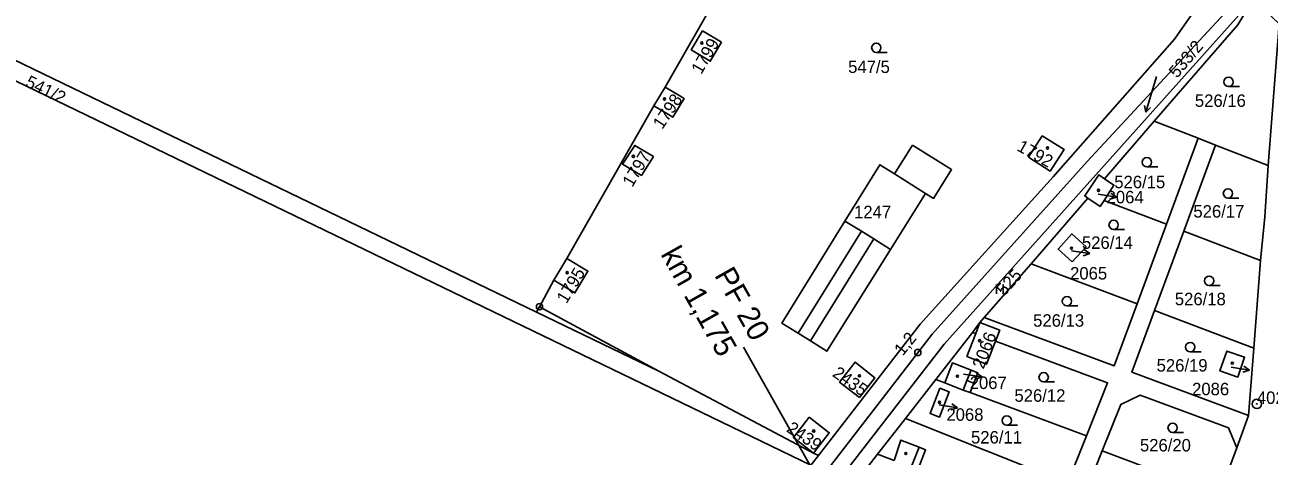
# Model space of a CAD drawing. Extents: x -555757 to -553364, y -1100723 to -1096439.
# Drawn here: x -554058.6 to -553858.9, y -1099803.9 to -1099734.7 of the extents above; entities that cross this region are included whole.
import ezdxf

# ---------------------------------------------------------------- set-up
doc = ezdxf.new("R2010")
doc.units = 0
for name, color, linetype in [('00_NÁVRH - 0.18 mm', 7, 'Continuous'), ('00_NÁVRH - 0.50 mm', 7, 'Continuous'), ('00_NÁVRH - Popis', 7, 'Continuous'), ('00_NÁVRH - Řezy', 7, 'Continuous'), ('BUDOVY', 7, 'Continuous'), ('C$SLO$PARCELY', 7, 'Continuous'), ('CISLO_PBPP', 7, 'Continuous'), ('HRANICE$PARCELY', 7, 'Continuous'), ('HRANICE$POROSTU', 7, 'Continuous'), ('PLOTY', 7, 'Continuous'), ('SLOUPY', 7, 'Continuous'), ('SLUCKOV$$C$RA', 7, 'Continuous'), ('STROMY', 7, 'Continuous'), ('VSTUP', 7, 'Continuous'), ('ZNA$KY$KULTUR', 7, 'Continuous')]:
    doc.layers.add(name, color=color, linetype=linetype)

# ---------------------------------------------------------------- blocks, each defined once
blk = doc.blocks.new('1$01')
at = {"layer": 'SLOUPY'}
for radius in [0.75, 0.032]:
    blk.add_circle((0, 0), radius, dxfattribs=at)
blk = doc.blocks.new('4$02')
at = {"layer": 'SLOUPY'}
blk.add_circle((0, 0), 0.175, dxfattribs=at)
blk = doc.blocks.new('1029')
at = {"layer": 'PLOTY'}
for p, q in [((0, 0), (2.964, -0.468)), ((2.964, -0.468), (2.052, 0.182)), ((2.964, -0.468), (1.897, -0.807))]:
    blk.add_line(p, q, dxfattribs=at)
blk = doc.blocks.new('3$04')
at = {"layer": 'ZNA$KY$KULTUR'}
blk.add_line((0.01, 0), (1.76, 0), dxfattribs=at)
blk.add_circle((0.01, 0.75), 0.75, dxfattribs=at)
blk = doc.blocks.new('3$06')
at = {"layer": 'SLOUPY'}
for p, q in [((-0.517, 0.235), (-0.517, 1.735)), ((0.517, 0.235), (0.517, 1.735))]:
    blk.add_line(p, q, dxfattribs=at)
blk = doc.blocks.new('8$02')
at = {"layer": 'ZNA$KY$KULTUR'}
for p, q in [((0.864, 2.855), (-0.89, -2.882)), ((-0.89, -2.882), (-1.083, -1.802)), ((-0.89, -2.882), (-0.125, -2.095))]:
    blk.add_line(p, q, dxfattribs=at)
blk = doc.blocks.new('1$05')
at = {"layer": 'SLOUPY'}
for radius in [0.5, 0.032]:
    blk.add_circle((0, 0), radius, dxfattribs=at)

msp = doc.modelspace()

# ---------------------------------------------------------------- linework, layer by layer
at = {"layer": '00_NÁVRH - 0.18 mm'}
msp.add_lwpolyline([(-554021.29, -1099939.52), (-554013.83, -1099925), (-554000.19, -1099901.94), (-553991.44, -1099884.82), (-553981.64, -1099867.37), (-553978.87, -1099863.78), (-553964.23, -1099845.81), (-553946.91, -1099823.19), (-553931.16, -1099807.8), (-553913.02, -1099784.31), (-553888.14, -1099756.58), (-553861.85, -1099728.23)], dxfattribs=at)
at = {"layer": '00_NÁVRH - 0.50 mm'}
msp.add_circle((-553915.3, -1099787.26), 0.5, dxfattribs=at)
at = {"layer": '00_NÁVRH - Řezy'}
msp.add_line((-553943.26, -1099786.41), (-553928.62, -1099812.39), dxfattribs=at)
at = {"layer": 'HRANICE$PARCELY'}
for p, q in [((-553930.27, -1099699.87), (-553955.86, -1099744.63)), ((-554139.3, -1099705.39), (-553932.48, -1099805.38)), ((-553955.86, -1099744.63), (-553957.65, -1099747.64)), ((-553957.65, -1099747.64), (-553971.65, -1099772.17)), ((-553885.34, -1099759.37), (-553877.35, -1099750.14)), ((-553870.34, -1099752.87), (-553877.35, -1099750.14)), ((-553875.42, -1099766.68), (-553870.34, -1099752.87)), ((-553867.55, -1099753.96), (-553872.62, -1099767.76)), ((-553870.34, -1099752.87), (-553867.55, -1099753.96)), ((-553867.55, -1099753.96), (-553859.1, -1099757.24)), ((-553897.14, -1099773), (-553888.02, -1099762.47)), ((-553875.42, -1099766.68), (-553885.42, -1099762.83)), ((-553880.12, -1099779.46), (-553875.42, -1099766.68)), ((-553872.62, -1099767.76), (-553877.31, -1099780.53)), ((-553872.62, -1099767.76), (-553860.3, -1099772.5)), ((-553971.65, -1099772.17), (-553973.74, -1099775.66)), ((-553904.64, -1099781.66), (-553897.14, -1099773)), ((-553880.12, -1099779.46), (-553897.14, -1099773)), ((-553861.4, -1099786.56), (-553860.3, -1099772.5)), ((-553973.74, -1099775.66), (-553976.03, -1099779.92)), ((-553905.33, -1099782.46), (-553904.64, -1099781.66)), ((-553877.31, -1099780.53), (-553861.4, -1099786.56)), ((-553912.43, -1099791.58), (-553906.55, -1099784.03)), ((-553905.33, -1099782.46), (-553906.55, -1099784.03)), ((-553862.25, -1099797.38), (-553861.4, -1099786.56)), ((-553917.29, -1099797.84), (-553912.43, -1099791.58)), ((-553910.96, -1099792.15), (-553912.43, -1099791.58)), ((-553888.24, -1099800.64), (-553906.93, -1099793.71)), ((-553921.77, -1099803.59), (-553917.29, -1099797.84)), ((-553891.27, -1099808.26), (-553917.29, -1099797.84)), ((-553864.13, -1099802.55), (-553862.25, -1099797.38)), ((-553891.27, -1099808.26), (-553888.24, -1099800.64)), ((-553931.27, -1099803.82), (-553932.48, -1099805.38)), ((-553925.95, -1099808.97), (-553921.77, -1099803.59)), ((-553919.13, -1099804.61), (-553921.77, -1099803.59)), ((-553885.73, -1099803.07), (-553889.33, -1099812.03)), ((-553885.73, -1099803.07), (-553866.89, -1099810.11)), ((-553866.89, -1099810.11), (-553864.13, -1099802.55))]:
    msp.add_line(p, q, dxfattribs=at)
for points in [[(-553976.03, -1099779.92), (-553976.49, -1099780.77), (-554138.23, -1099702.58)], [(-553861.5, -1099730.48), (-553911.1, -1099785.91), (-553936.82, -1099819.17)], [(-553877.35, -1099750.14), (-553863.93, -1099734.63), (-553861.5, -1099730.48)], [(-553859.1, -1099757.24), (-553857.32, -1099734.5), (-553861.5, -1099730.48)], [(-553871.02, -1099732.51), (-553874.13, -1099736.94), (-553893.58, -1099759.08)], [(-553946.8, -1099737.45), (-553949.86, -1099735.62), (-553951.68, -1099738.67), (-553948.62, -1099740.5), (-553946.8, -1099737.45)], [(-553957.65, -1099747.64), (-553955.3, -1099749.04), (-553954.61, -1099749.45), (-553952.82, -1099746.45), (-553953.5, -1099746.04), (-553955.86, -1099744.63)], [(-553957.73, -1099755.8), (-553960.75, -1099754), (-553962.68, -1099757.03), (-553959.66, -1099758.83), (-553957.73, -1099755.8)], [(-553916.14, -1099753.97), (-553919.03, -1099758.6), (-553921.42, -1099757.11), (-553927, -1099766.15), (-553937.14, -1099782.53), (-553934.52, -1099784.17), (-553932.55, -1099785.4), (-553929.9, -1099787.06), (-553919.68, -1099770.72), (-553914.05, -1099761.71), (-553912.77, -1099762.51), (-553909.88, -1099757.88), (-553916.14, -1099753.97)], [(-553897.56, -1099755.9), (-553894.08, -1099758.15), (-553891.84, -1099754.66), (-553895.33, -1099752.48), (-553897.56, -1099755.9)], [(-553860.3, -1099772.5), (-553859.62, -1099765.49), (-553859.1, -1099757.24)], [(-553893.58, -1099759.08), (-553914.95, -1099782.72), (-553931.27, -1099803.82)], [(-553885.34, -1099759.37), (-553886.27, -1099758.75), (-553888.53, -1099762.13), (-553888.02, -1099762.47)], [(-553885.42, -1099762.83), (-553883.83, -1099760.39), (-553885.34, -1099759.37)], [(-553888.02, -1099762.47), (-553886.05, -1099763.8), (-553885.42, -1099762.83)], [(-553890.52, -1099772.73), (-553888.31, -1099770.31), (-553890.59, -1099768.23), (-553892.8, -1099770.65), (-553890.52, -1099772.73)], [(-553973.74, -1099775.66), (-553970.35, -1099777.69), (-553968.26, -1099774.2), (-553971.65, -1099772.17)], [(-553931.27, -1099803.82), (-553932.03, -1099803.41), (-553956.88, -1099790.26), (-553976.03, -1099779.92)], [(-553904.64, -1099781.66), (-553883.77, -1099789.4), (-553880.12, -1099779.46)], [(-553877.31, -1099780.53), (-553880.96, -1099790.44), (-553862.25, -1099797.38)], [(-553906.55, -1099784.03), (-553906.02, -1099784.23), (-553907.45, -1099787.92)], [(-553902.84, -1099785.42), (-553902.17, -1099783.69), (-553905.33, -1099782.46)], [(-553907.45, -1099787.92), (-553904.29, -1099789.14), (-553902.84, -1099785.42)], [(-553888.24, -1099800.64), (-553884.86, -1099792.14), (-553902.84, -1099785.42)], [(-553863.97, -1099791.22), (-553862.86, -1099788.04), (-553865.69, -1099787.03), (-553866.82, -1099790.21), (-553863.97, -1099791.22)], [(-553924.69, -1099794.51), (-553922.22, -1099791.32), (-553925.39, -1099788.84), (-553927.87, -1099792.01), (-553924.69, -1099794.51)], [(-553906.93, -1099793.71), (-553906.34, -1099792.19), (-553905.69, -1099790.52), (-553906.77, -1099790.1), (-553909.72, -1099788.95), (-553910.96, -1099792.15)], [(-553911.76, -1099793), (-553913.34, -1099797.06), (-553911.84, -1099797.64), (-553910.27, -1099793.58), (-553911.76, -1099793)], [(-553910.96, -1099792.15), (-553908.01, -1099793.3), (-553906.93, -1099793.71)], [(-553864.13, -1099802.55), (-553865.47, -1099799.38), (-553879.6, -1099794.1), (-553882.73, -1099795.6), (-553885.73, -1099803.07)], [(-553932.76, -1099797.67), (-553935.27, -1099800.94), (-553932.03, -1099803.41), (-553929.53, -1099800.14), (-553932.76, -1099797.67)], [(-553915.31, -1099806.1), (-553914.05, -1099802.87), (-553915.11, -1099802.46), (-553918.06, -1099801.32), (-553919.13, -1099804.61)]]:
    msp.add_lwpolyline(points, dxfattribs=at)
at = {"layer": 'SLUCKOV$$C$RA'}
for p, q in [((-553919.03, -1099758.6), (-553914.05, -1099761.71)), ((-553934.52, -1099784.17), (-553924.35, -1099767.8)), ((-553927, -1099766.15), (-553924.35, -1099767.8)), ((-553924.35, -1099767.8), (-553922.37, -1099769.03)), ((-553922.37, -1099769.03), (-553932.55, -1099785.4)), ((-553922.37, -1099769.03), (-553919.68, -1099770.72)), ((-553956.88, -1099790.26), (-553976.49, -1099780.77)), ((-553905.33, -1099782.46), (-553906.02, -1099784.23)), ((-553908.01, -1099793.3), (-553907.42, -1099791.78)), ((-553907.42, -1099791.78), (-553906.77, -1099790.1)), ((-553907.42, -1099791.78), (-553906.34, -1099792.19)), ((-553916.36, -1099805.69), (-553915.11, -1099802.46))]:
    msp.add_line(p, q, dxfattribs=at)

# ---------------------------------------------------------------- block references
at = {"layer": 'BUDOVY'}
for p in [(-553949.98, -1099737.55), (-553955.97, -1099746.56), (-553960.96, -1099755.75), (-553894.5, -1099754.43), (-553886.31, -1099761.22), (-553890.65, -1099770.51), (-553971.58, -1099774.43), (-553905.38, -1099785.37), (-553864.84, -1099788.97), (-553924.68, -1099791.01), (-553908.95, -1099791.07), (-553911.83, -1099795.27), (-553932.01, -1099799.86), (-553917.24, -1099803.49)]:
    msp.add_blockref('4$02', p, dxfattribs=at)
at = {"layer": 'HRANICE$POROSTU'}
msp.add_blockref('1$01', (-553860.89, -1099795.52), dxfattribs=at)
at = {"layer": 'PLOTY'}
for p in [(-553886.37, -1099761.84), (-553890.65, -1099770.92), (-553865.02, -1099789.62), (-553907.97, -1099790.72), (-553911.88, -1099795.68)]:
    msp.add_blockref('1029', p, dxfattribs=at)
at = {"layer": 'VSTUP'}
msp.add_blockref('1$05', (-553976.03, -1099779.92), dxfattribs=at)
at = {"layer": 'ZNA$KY$KULTUR'}
for name, p in [('3$04', (-553921.98, -1099739.07)), ('8$02', (-553877.84, -1099745.8)), ('3$04', (-553865.45, -1099744.57)), ('3$04', (-553878.55, -1099757.46)), ('3$04', (-553865.54, -1099762.47)), ('3$04', (-553883.89, -1099767.53)), ('3$04', (-553868.56, -1099776.49)), ('3$06', (-553902.14, -1099778.1)), ('3$04', (-553891.38, -1099779.79)), ('3$04', (-553871.6, -1099787.15)), ('3$04', (-553895.12, -1099791.99)), ('3$04', (-553901.05, -1099798.95)), ('3$04', (-553874.42, -1099800.09))]:
    msp.add_blockref(name, p, dxfattribs=at)

# ---------------------------------------------------------------- texts
at = {"layer": '00_NÁVRH - Popis'}
msp.add_text('1,2', height=2, rotation=51.374, dxfattribs=at).set_placement((-553917.71, -1099787.91))
at = {"layer": '00_NÁVRH - Řezy'}
for s, p in [('km 1,175', (-553956.65, -1099771.47)), ('PF 20', (-553948.04, -1099774.83))]:
    msp.add_text(s, height=3.5, rotation=299.3905, dxfattribs=at).set_placement(p)
at = {"layer": 'C$SLO$PARCELY'}
for s, rotation, p in [('1799', 60, (-553950.06, -1099742.72)), ('533/2', 50, (-553873.69, -1099743.32)), ('541/2', 334, (-554058.69, -1099744.47)), ('1798', 56, (-553956.32, -1099751.54)), ('1792', 331, (-553899.55, -1099754.75)), ('1797', 59, (-553961.14, -1099760.84)), ('1795', 59, (-553971.69, -1099779.53)), ('525', 48, (-553901.43, -1099778.29)), ('2066', 69, (-553904.77, -1099790.03)), ('2435', 325, (-553929.15, -1099790.98)), ('2439', 326, (-553936.54, -1099799.86))]:
    msp.add_text(s, height=2, rotation=rotation, dxfattribs=at).set_placement(p)
for s, p in [('547/5', (-553926.49, -1099742.38)), ('526/16', (-553870.84, -1099747.82)), ('526/15', (-553883.78, -1099760.88)), ('2064', (-553885.01, -1099763.31)), ('1247', (-553925.54, -1099765.7)), ('526/17', (-553871.08, -1099765.6)), ('526/14', (-553888.97, -1099770.62)), ('2065', (-553890.87, -1099775.54)), ('526/18', (-553874.06, -1099779.67)), ('526/13', (-553896.8, -1099783.12)), ('526/19', (-553876.98, -1099790.33)), ('2067', (-553906.98, -1099793.13)), ('526/12', (-553899.8, -1099795.17)), ('2086', (-553871.29, -1099794.13)), ('2068', (-553910.72, -1099798.23)), ('526/11', (-553906.77, -1099801.88)), ('526/20', (-553879.66, -1099803.15))]:
    msp.add_text(s, height=2, dxfattribs=at).set_placement(p)
at = {"layer": 'CISLO_PBPP'}
msp.add_text('4023', height=2, dxfattribs=at).set_placement((-553860.89, -1099795.52))
at = {"layer": 'STROMY'}
msp.add_text('238.71', height=0.1, dxfattribs=at).set_placement((-553861.17, -1099795.57))

doc.saveas('drawing.dxf')
